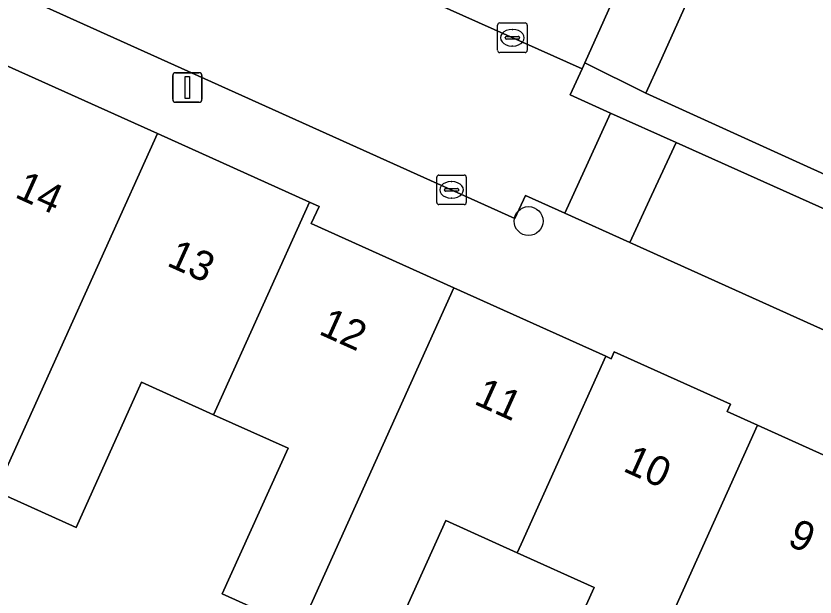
# Model space of a CAD drawing. Extents: x 161838 to 162344, y 381620 to 382160.
# Drawn here: x 162173.63 to 162200.67, y 381678.21 to 381697.89 of the extents above; entities that cross this region are included whole.
import ezdxf

# ---------------------------------------------------------------- set-up
doc = ezdxf.new("R2010")
doc.units = 0
for name, color, linetype in [('IMGEO_Boom', 7, 'Continuous'), ('IMGEO_Erf', 7, 'Continuous'), ('IMGEO_Groenvoorziening', 7, 'Continuous'), ('IMGEO_Kolk', 7, 'Continuous'), ('IMGEO_Lichtmast', 7, 'Continuous'), ('IMGEO_Pand', 7, 'Continuous'), ('IMGEO_Pand_nummerreeks', 7, 'Continuous'), ('IMGEO_Parkeervlak_open', 7, 'Continuous'), ('IMGEO_Rijbaan_lokaal_open', 7, 'Continuous'), ('IMGEO_Voetpad_open', 7, 'Continuous')]:
    doc.layers.add(name, color=color, linetype=linetype)

msp = doc.modelspace()

# ---------------------------------------------------------------- linework, layer by layer
at = {"layer": 'IMGEO_Boom'}
msp.add_circle((162190.979, 381690.942), 0.489, dxfattribs=at)
at = {"layer": 'IMGEO_Erf'}
for points in [[(162183.238, 381677.127), (162180.611, 381678.312), (162182.838, 381683.249), (162180.319, 381684.385), (162177.883, 381685.484), (162175.666, 381680.567), (162172.96, 381681.787)], [(162190.982, 381673.625), (162193.196, 381678.533), (162190.591, 381679.708), (162188.176, 381680.797), (162185.966, 381675.897)]]:
    msp.add_lwpolyline(points, dxfattribs=at)
at = {"layer": 'IMGEO_Groenvoorziening'}
msp.add_lwpolyline([(162206.127, 381698.125), (162203.137, 381698.864), (162201.889, 381700.486), (162200.989, 381702.599), (162198.743, 381703.712), (162195.428, 381696.339), (162194.952, 381695.269), (162206.336, 381690.092)], dxfattribs=at)
at = {"layer": 'IMGEO_Kolk'}
for p, q in [((162189.931, 381696.724), (162189.931, 381697.576)), ((162190.006, 381697.65), (162190.858, 381697.65)), ((162190.419, 381697.43), (162190.444, 381697.43)), ((162190.932, 381697.576), (162190.932, 381696.724)), ((162190.19, 381697.144), (162190.19, 381697.156)), ((162190.233, 381697.193), (162190.631, 381697.193)), ((162190.674, 381697.156), (162190.674, 381697.144)), ((162190.628, 381697.107), (162190.23, 381697.107)), ((162190.442, 381696.87), (162190.417, 381696.87)), ((162190.858, 381696.65), (162190.006, 381696.65)), ((162187.871, 381691.572), (162187.871, 381692.424)), ((162187.946, 381692.498), (162188.798, 381692.498)), ((162188.359, 381692.278), (162188.384, 381692.278)), ((162188.872, 381692.424), (162188.872, 381691.572)), ((162188.13, 381691.992), (162188.13, 381692.004)), ((162188.173, 381692.041), (162188.571, 381692.041)), ((162188.614, 381692.004), (162188.614, 381691.992)), ((162188.568, 381691.955), (162188.17, 381691.955)), ((162188.382, 381691.718), (162188.357, 381691.718)), ((162188.798, 381691.498), (162187.946, 381691.498))]:
    msp.add_line(p, q, dxfattribs=at)
for points in [[(162189.931, 381696.724), (162189.931, 381697.576)], [(162190.006, 381697.65), (162190.858, 381697.65)], [(162190.932, 381697.576), (162190.932, 381696.724)], [(162190.858, 381696.65), (162190.006, 381696.65)], [(162187.871, 381691.572), (162187.871, 381692.424)], [(162187.946, 381692.498), (162188.798, 381692.498)], [(162188.872, 381692.424), (162188.872, 381691.572)], [(162188.798, 381691.498), (162187.946, 381691.498)]]:
    msp.add_lwpolyline(points, dxfattribs=at)
for centre, radius, start, end in [((162190.008, 381697.574), 0.0765, 91.552, 178.448), ((162190.008, 381697.574), 0.0765, 91.552, 178.448), ((162190.856, 381697.574), 0.0765, 1.552, 88.448), ((162190.856, 381697.574), 0.0765, 1.552, 88.448), ((162190.23, 381697.153), 0.0403, 85.8775, 175.7526), ((162190.227, 381697.143), 0.0366, 178.938, 274.7102), ((162190.631, 381697.15), 0.043, 264.8664, 352.4533), ((162190.635, 381697.155), 0.0386, 1.7309, 96.639), ((162190.008, 381696.726), 0.0765, 181.552, 268.448), ((162190.008, 381696.726), 0.0765, 181.552, 268.448), ((162190.856, 381696.726), 0.0765, 271.552, 358.448), ((162190.856, 381696.726), 0.0765, 271.552, 358.448), ((162187.948, 381692.422), 0.0765, 91.552, 178.448), ((162187.948, 381692.422), 0.0765, 91.552, 178.448), ((162188.796, 381692.422), 0.0765, 1.552, 88.448), ((162188.796, 381692.422), 0.0765, 1.552, 88.448), ((162188.17, 381692.001), 0.0403, 85.8775, 175.7526), ((162188.167, 381691.991), 0.0366, 178.938, 274.7102), ((162188.571, 381691.998), 0.043, 264.8664, 352.4533), ((162188.575, 381692.003), 0.0386, 1.7309, 96.639), ((162187.948, 381691.574), 0.0765, 181.552, 268.448), ((162187.948, 381691.574), 0.0765, 181.552, 268.448), ((162188.796, 381691.574), 0.0765, 271.552, 358.448), ((162188.796, 381691.574), 0.0765, 271.552, 358.448)]:
    msp.add_arc(centre, radius, start, end, dxfattribs=at)
for centre, major_axis, ratio, start_param, end_param in [((162190.418, 381697.15), (-0.387, 0.002), 0.722429, 4.712389, 7.853982), ((162190.443, 381697.15), (-0.39, 0.002), 0.717154, 1.570796, 4.712389), ((162188.358, 381691.998), (-0.387, 0.002), 0.722429, 4.712389, 7.853982), ((162188.383, 381691.998), (-0.39, 0.002), 0.717154, 1.570796, 4.712389)]:
    msp.add_ellipse(centre, major_axis=major_axis, ratio=ratio, start_param=start_param, end_param=end_param, dxfattribs=at)
at = {"layer": 'IMGEO_Lichtmast'}
for p, q in [((162178.935, 381695.066), (162178.935, 381695.866)), ((162178.935, 381695.866), (162178.935, 381695.066)), ((162179.035, 381695.966), (162179.825, 381695.966)), ((162179.825, 381695.966), (162179.035, 381695.966)), ((162179.925, 381695.866), (162179.925, 381695.066)), ((162179.925, 381695.066), (162179.925, 381695.866)), ((162179.825, 381694.966), (162179.035, 381694.966)), ((162179.035, 381694.966), (162179.825, 381694.966))]:
    msp.add_line(p, q, dxfattribs=at)
msp.add_lwpolyline([(162179.355, 381695.841), (162179.505, 381695.841), (162179.505, 381695.091), (162179.355, 381695.091), (162179.355, 381695.841)], dxfattribs=at)
for centre, start, end in [((162179.035, 381695.866), 90, 180), ((162179.035, 381695.866), 90, 180), ((162179.825, 381695.866), 0, 90), ((162179.825, 381695.866), 360, 90), ((162179.035, 381695.066), 180, 270), ((162179.035, 381695.066), 180, 270), ((162179.825, 381695.066), 270, 0), ((162179.825, 381695.066), 270, 0)]:
    msp.add_arc(centre, 0.1, start, end, dxfattribs=at)
at = {"layer": 'IMGEO_Pand'}
for points in [[(162178.421, 381693.905), (162173.276, 381696.224), (162173.017, 381695.65), (162170.026, 381689.013), (162172.497, 381687.899), (162170.285, 381682.994), (162172.96, 381681.787), (162173.109, 381682.117)], [(162183.565, 381691.585), (162178.421, 381693.905), (162173.109, 381682.117), (162172.96, 381681.787), (162175.666, 381680.567), (162177.883, 381685.484), (162180.319, 381684.385), (162180.431, 381684.633)], [(162183.238, 381677.127), (162183.402, 381677.49), (162188.445, 381688.68), (162183.625, 381690.854), (162183.889, 381691.439), (162183.565, 381691.585), (162180.431, 381684.633), (162180.319, 381684.385), (162182.838, 381683.249), (162180.611, 381678.312)], [(162190.591, 381679.708), (162190.724, 381680.003), (162193.589, 381686.361), (162188.445, 381688.68), (162183.402, 381677.49), (162183.238, 381677.127), (162185.966, 381675.897), (162188.176, 381680.797)], [(162190.591, 381679.708), (162193.196, 381678.533), (162190.982, 381673.625), (162193.523, 381672.479), (162193.693, 381672.857), (162198.726, 381684.025), (162197.7, 381684.487), (162197.816, 381684.743), (162193.881, 381686.518), (162193.773, 381686.278), (162193.589, 381686.361), (162190.724, 381680.003)], [(162203.869, 381681.706), (162198.726, 381684.025), (162193.693, 381672.857), (162193.523, 381672.479), (162196.236, 381671.255), (162198.461, 381676.191), (162199.554, 381675.698), (162200.911, 381675.128), (162201.019, 381675.369)]]:
    msp.add_lwpolyline(points, close=True, dxfattribs=at)
at = {"layer": 'IMGEO_Parkeervlak_open'}
msp.add_lwpolyline([(162172.71, 381710.455), (162170.848, 381706.126), (162170.775, 381705.955), (162192.789, 381696.092), (162192.884, 381696.303), (162194.748, 381700.457)], close=True, dxfattribs=at)
at = {"layer": 'IMGEO_Rijbaan_lokaal_open'}
for points in [[(162168.836, 381701.751), (162168.498, 381700.961), (162190.513, 381691.034), (162190.876, 381691.811), (162192.206, 381691.211), (162192.992, 381692.935), (162193.752, 381694.6), (162192.389, 381695.213), (162192.789, 381696.092), (162170.775, 381705.955), (162170.425, 381705.076), (162168.827, 381705.791), (162168.089, 381704.089), (162167.365, 381702.42)], [(162192.206, 381691.211), (162194.402, 381690.217), (162195.139, 381691.807), (162195.971, 381693.604), (162193.752, 381694.6), (162192.992, 381692.935)]]:
    msp.add_lwpolyline(points, close=True, dxfattribs=at)
msp.add_lwpolyline([(162205.859, 381689.162), (162195.971, 381693.604), (162195.139, 381691.807), (162194.402, 381690.217), (162207.784, 381684.172)], dxfattribs=at)
at = {"layer": 'IMGEO_Voetpad_open'}
msp.add_lwpolyline([(162174.526, 381714.664), (162174.065, 381714.873), (162173.667, 381715.053), (162173.385, 381714.496), (162170.977, 381715.518), (162169.768, 381712.761), (162169.514, 381712.181), (162171.984, 381711.132), (162170.37, 381707.654), (162169.339, 381708.142), (162168.826, 381707.033), (162170.848, 381706.126), (162172.71, 381710.455), (162194.748, 381700.457), (162192.884, 381696.303), (162194.952, 381695.269), (162195.428, 381696.339), (162198.743, 381703.712), (162191.198, 381707.111)], close=True, dxfattribs=at)
for points in [[(162207.784, 381684.172), (162194.402, 381690.217), (162192.206, 381691.211), (162190.876, 381691.811), (162190.513, 381691.034), (162168.498, 381700.961)], [(162173.276, 381696.224), (162178.421, 381693.905), (162183.565, 381691.585), (162183.889, 381691.439), (162183.625, 381690.854), (162188.445, 381688.68), (162193.589, 381686.361), (162193.773, 381686.278), (162193.881, 381686.518), (162197.816, 381684.743), (162197.7, 381684.487), (162198.726, 381684.025), (162203.869, 381681.706), (162207.271, 381680.172), (162210.191, 381682.169)], [(162194.952, 381695.269), (162192.884, 381696.303), (162192.789, 381696.092), (162192.389, 381695.213), (162193.752, 381694.6), (162195.971, 381693.604), (162205.859, 381689.162)], [(162206.336, 381690.092), (162194.952, 381695.269)]]:
    msp.add_lwpolyline(points, dxfattribs=at)

# ---------------------------------------------------------------- texts
at = {"layer": 'IMGEO_Pand_nummerreeks'}
for s, rotation, p in [('14', 335.7467, (162173.555, 381691.764)), ('13', 335.7457, (162178.699, 381689.447)), ('12', 335.7457, (162183.841, 381687.13)), ('11', 335.7457, (162189.093, 381684.764)), ('10', 335.7457, (162194.137, 381682.491)), ('9', 335.7457, (162199.697, 381679.985))]:
    msp.add_text(s, height=1, rotation=rotation, dxfattribs=at).set_placement(p)

doc.saveas('drawing.dxf')
